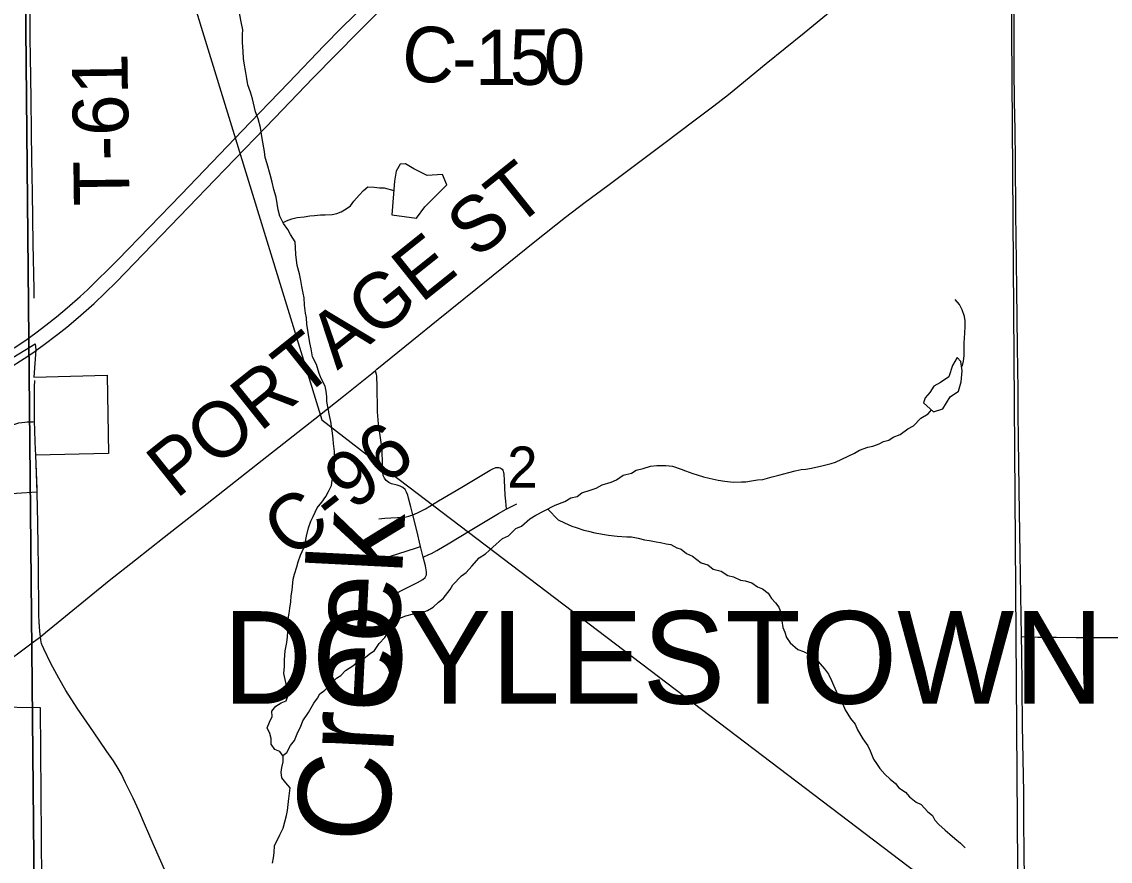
# Model space of a CAD drawing. Extents: x 0 to 34, y -5 to 22.
# Drawn here: x 4.121 to 5.234, y 15.66 to 16.518 of the extents above; entities that cross this region are included whole.
import ezdxf

# ---------------------------------------------------------------- set-up
doc = ezdxf.new("R2010")
doc.units = 0
for name, color, linetype in [('GM_X_City_Street', 7, 'Continuous'), ('GM_X_Corporation', 7, 'Continuous'), ('GM_X_Corporation_Text', 7, 'Continuous'), ('GM_X_County_Road', 7, 'Continuous'), ('GM_X_County_Road_Text', 7, 'Continuous'), ('GM_X_Minor_Lake', 7, 'Continuous'), ('GM_X_Minor_River', 7, 'Continuous'), ('GM_X_Minor_River_Text', 7, 'Continuous'), ('GM_X_Rail_Line', 7, 'Continuous'), ('GM_X_Section', 7, 'Continuous'), ('GM_X_Section_Text', 7, 'Continuous'), ('GM_X_State_Route', 7, 'Continuous'), ('GM_X_Township_Road', 7, 'Continuous'), ('GM_X_Township_Road_Text', 7, 'Continuous')]:
    doc.layers.add(name, color=color, linetype=linetype)

msp = doc.modelspace()

# ---------------------------------------------------------------- linework, layer by layer
at = {"layer": 'GM_X_City_Street'}
msp.add_lwpolyline([(3.9694, 16.021), (3.9748, 16.024), (3.98, 16.0275), (3.9848, 16.0315), (3.9892, 16.0358), (4.002, 16.0495), (4.0089, 16.0558), (4.0138, 16.0596), (4.0189, 16.0632), (4.027, 16.0678), (4.0382, 16.0733), (4.0666, 16.0862), (4.1006, 16.1016), (4.1092, 16.1052), (4.1151, 16.1072), (4.1181, 16.1079), (4.1243, 16.1088), (4.1266, 16.109), (4.1323, 16.1092), (4.1342, 16.1093)], dxfattribs=at)
at = {"layer": 'GM_X_Corporation'}
for points in [[(4.0677, 16.1481), (4.1346, 16.189), (4.1354, 16.1826), (4.1334, 16.1549), (4.2082, 16.1569), (4.2096, 16.0766), (4.1352, 16.075), (4.1366, 16.0371), (4.0945, 16.0344)], [(4.0447, 15.8182), (4.1399, 15.8168), (4.1417, 15.5953), (4.1319, 15.0927)]]:
    msp.add_lwpolyline(points, dxfattribs=at)
at = {"layer": 'GM_X_County_Road'}
for points in [[(4.4841, 16.1629), (4.52, 16.1921), (4.5466, 16.2137), (4.5853, 16.2449), (4.6457, 16.2937), (4.6771, 16.3186), (4.697, 16.3338), (4.7202, 16.3508), (4.7788, 16.3947), (4.8083, 16.4171), (4.8287, 16.4323), (4.8437, 16.4441), (4.8822, 16.4757), (4.9208, 16.5071), (4.9497, 16.5307), (4.9762, 16.5523), (4.9797, 16.5552)], [(5.1431, 15.8894), (5.1418, 15.9739), (5.1415, 15.9955), (5.1408, 16.0387), (5.1404, 16.0677), (5.1401, 16.089), (5.1399, 16.1202), (5.1396, 16.1419), (5.139, 16.1855), (5.1384, 16.2446), (5.1381, 16.273), (5.1373, 16.3223), (5.1372, 16.3402), (5.1371, 16.3594), (5.137, 16.3829), (5.1368, 16.4012), (5.1367, 16.4083), (5.1361, 16.4365), (5.1357, 16.4701), (5.1356, 16.5048), (5.1355, 16.5422), (5.1353, 16.5515), (5.1352, 16.5572)], [(4.1401, 15.8892), (4.1453, 15.8936), (4.2104, 15.9466), (4.2372, 15.968), (4.2665, 15.9911), (4.3106, 16.0256), (4.3619, 16.066), (4.4255, 16.116), (4.4499, 16.1352), (4.4789, 16.1587), (4.4826, 16.1617), (4.4841, 16.1629)], [(4.0964, 15.8566), (4.1332, 15.884), (4.1401, 15.8892)], [(5.1481, 15.4093), (5.148, 15.4361), (5.1478, 15.4766), (5.1478, 15.5357), (5.1472, 15.5849), (5.1465, 15.6221), (5.1459, 15.666), (5.1455, 15.703), (5.1454, 15.7299), (5.1443, 15.7983), (5.1439, 15.8386), (5.1434, 15.8728), (5.1431, 15.8894)]]:
    msp.add_lwpolyline(points, dxfattribs=at)
at = {"layer": 'GM_X_Minor_Lake'}
for points in [[(4.4994, 16.321), (4.5245, 16.3174), (4.5331, 16.3292), (4.5441, 16.3399), (4.5557, 16.3514), (4.5511, 16.362), (4.5356, 16.3612), (4.5218, 16.3679), (4.5135, 16.3731), (4.5078, 16.3727), (4.5037, 16.3655), (4.5022, 16.3552)], [(4.5022, 16.3552), (4.4994, 16.321)], [(5.0532, 16.1194), (5.0626, 16.1225), (5.0701, 16.1347), (5.0788, 16.1405), (5.0814, 16.15), (5.0825, 16.1614), (5.0812, 16.1709), (5.0774, 16.175), (5.0726, 16.1666), (5.0688, 16.1552), (5.0602, 16.1495), (5.0534, 16.1456), (5.0496, 16.1391), (5.0447, 16.1338), (5.0429, 16.1284)], [(5.0429, 16.1284), (5.0532, 16.1194)]]:
    msp.add_lwpolyline(points, dxfattribs=at)
at = {"layer": 'GM_X_Minor_River'}
for points in [[(4.3923, 15.8348), (4.391, 15.8424), (4.3889, 15.8515), (4.3896, 15.8587), (4.3898, 15.8656), (4.3904, 15.8747), (4.3921, 15.8835), (4.3928, 15.8892), (4.393, 15.8946), (4.3929, 15.9003), (4.3932, 15.906), (4.3946, 15.9129), (4.3952, 15.9186), (4.3963, 15.9251), (4.3965, 15.9312), (4.3976, 15.9369), (4.3985, 15.948), (4.3999, 15.9533), (4.4024, 15.9606), (4.4038, 15.9659), (4.406, 15.9728), (4.4093, 15.9801), (4.4107, 15.9851), (4.4121, 15.992), (4.4142, 16.0008), (4.4167, 16.0073), (4.4189, 16.0123), (4.423, 16.0211), (4.4278, 16.0269), (4.4319, 16.0327), (4.4348, 16.0377), (4.4377, 16.0439), (4.4384, 16.0492), (4.4405, 16.058), (4.4408, 16.0648), (4.4409, 16.0789), (4.4399, 16.0869), (4.4395, 16.0918), (4.4386, 16.0975), (4.4372, 16.1093), (4.4356, 16.1157), (4.4343, 16.1226), (4.433, 16.1298), (4.4329, 16.1347), (4.4321, 16.1404), (4.4312, 16.1457), (4.4272, 16.1533), (4.4252, 16.1585), (4.4224, 16.1676), (4.4184, 16.1755), (4.4168, 16.1839), (4.4155, 16.1899), (4.4138, 16.2006), (4.4125, 16.2089), (4.412, 16.2154), (4.4111, 16.2203), (4.4102, 16.2283), (4.4097, 16.2359), (4.4088, 16.2408), (4.4075, 16.2476), (4.4063, 16.2537), (4.405, 16.2605), (4.4025, 16.2692), (4.4012, 16.2802), (4.401, 16.2875), (4.4006, 16.2932), (4.3958, 16.3007), (4.3931, 16.306), (4.3888, 16.312), (4.3848, 16.3195), (4.3832, 16.3259), (4.381, 16.3388), (4.3786, 16.3468), (4.3769, 16.3544), (4.3749, 16.3623), (4.372, 16.3729), (4.37, 16.3794), (4.3691, 16.3858), (4.3669, 16.3991), (4.3652, 16.4101), (4.3627, 16.4192), (4.3599, 16.4264), (4.357, 16.4396), (4.355, 16.4464), (4.3521, 16.454), (4.3513, 16.4604), (4.35, 16.4665), (4.3483, 16.476), (4.3478, 16.4809), (4.3473, 16.4881), (4.3467, 16.4973), (4.3466, 16.5053), (4.3469, 16.5102), (4.3456, 16.5167), (4.3435, 16.5273)], [(4.3883, 16.3129), (4.3918, 16.3147), (4.3971, 16.3167), (4.4027, 16.3183), (4.4096, 16.3188), (4.4156, 16.3197), (4.4202, 16.3202), (4.4263, 16.3207), (4.4312, 16.3208), (4.4385, 16.3213), (4.443, 16.3221), (4.4475, 16.3241), (4.4528, 16.3269), (4.4573, 16.33), (4.4607, 16.3347), (4.4659, 16.3409), (4.4703, 16.3459), (4.4748, 16.3494), (4.4813, 16.3491), (4.4867, 16.3485), (4.4916, 16.3486), (4.5015, 16.3458)], [(5.0819, 16.1655), (5.0828, 16.1666), (5.0839, 16.1712), (5.0845, 16.1769), (5.0844, 16.1834), (5.0847, 16.1898), (5.085, 16.1948), (5.0852, 16.2001), (5.0855, 16.2062), (5.0854, 16.2123), (5.0849, 16.2169), (5.0825, 16.2237), (5.0797, 16.2293), (5.0754, 16.2342)], [(5.0326, 16.1051), (5.0401, 16.1129), (5.0476, 16.1172), (5.0512, 16.1212)], [(4.3878, 15.7676), (4.392, 15.7709), (4.3957, 15.7778), (4.3998, 15.7832), (4.4034, 15.7916), (4.406, 15.7966), (4.4085, 15.8032), (4.4141, 15.8116), (4.4196, 15.8212), (4.4233, 15.8263), (4.4259, 15.8309), (4.4308, 15.8344), (4.4427, 15.8468), (4.4472, 15.8496), (4.4521, 15.8546), (4.4596, 15.8593), (4.4641, 15.8632), (4.469, 15.8656), (4.4761, 15.8714), (4.4817, 15.8753), (4.4865, 15.8823), (4.4921, 15.8885), (4.4973, 15.8966), (4.5029, 15.902), (4.5077, 15.9082), (4.5138, 15.9106), (4.5217, 15.9126), (4.5271, 15.9127), (4.5358, 15.916), (4.5418, 15.9195), (4.547, 15.9245), (4.5519, 15.9284), (4.5589, 15.9377), (4.5619, 15.9423), (4.5705, 15.9516), (4.5754, 15.9548), (4.5813, 15.9614), (4.5888, 15.9699), (4.5952, 15.9742), (4.6026, 15.9808), (4.6127, 15.9897), (4.6188, 15.9925), (4.6262, 15.9999), (4.6319, 16.0023), (4.6405, 16.0097), (4.6465, 16.0136), (4.6552, 16.018), (4.6665, 16.0239), (4.6763, 16.0275), (4.6824, 16.0314), (4.6888, 16.0327), (4.6937, 16.0366), (4.7031, 16.0394), (4.7084, 16.0411), (4.7145, 16.0446), (4.7235, 16.0474), (4.7292, 16.0498), (4.736, 16.0545), (4.7443, 16.0566), (4.7492, 16.0597), (4.7564, 16.0614), (4.7639, 16.0638), (4.7704, 16.0643), (4.7795, 16.0645), (4.7864, 16.0639), (4.7952, 16.0606), (4.7998, 16.0588), (4.8071, 16.0563), (4.8117, 16.0548), (4.8182, 16.0527), (4.8239, 16.0513), (4.8331, 16.0495), (4.84, 16.0485), (4.8484, 16.0475), (4.8568, 16.0477), (4.8613, 16.0478), (4.867, 16.0487), (4.8731, 16.0499), (4.8788, 16.05), (4.8882, 16.0529), (4.8951, 16.0545), (4.9053, 16.0574), (4.9117, 16.059), (4.9178, 16.0603), (4.9227, 16.0608), (4.9284, 16.0616), (4.939, 16.0641), (4.9485, 16.0666), (4.953, 16.0678), (4.9595, 16.071), (4.9723, 16.0769), (4.9776, 16.0801), (4.9862, 16.0833), (4.9912, 16.0842), (4.9976, 16.0866), (5.0021, 16.0889), (5.0074, 16.0902), (5.0119, 16.0933), (5.0191, 16.0961), (5.027, 16.102), (5.0326, 16.1051)], [(4.659, 16.0199), (4.6695, 16.0087), (4.676, 16.0058), (4.6833, 16.0025), (4.6879, 16.0011), (4.6956, 15.9982), (4.7005, 15.9971), (4.707, 15.9954), (4.7208, 15.993), (4.7299, 15.992), (4.7395, 15.9914), (4.7444, 15.9915), (4.7513, 15.9901), (4.7578, 15.9883), (4.7628, 15.9877), (4.7696, 15.9863), (4.7742, 15.9856), (4.7799, 15.9842), (4.7845, 15.9835), (4.7907, 15.9802), (4.7953, 15.9788), (4.8007, 15.9743), (4.8068, 15.9718), (4.8157, 15.9647), (4.8226, 15.9629), (4.828, 15.9585), (4.8361, 15.9563), (4.843, 15.9519), (4.8487, 15.9505), (4.856, 15.9472), (4.8606, 15.9465), (4.8675, 15.9444), (4.8733, 15.9403), (4.8783, 15.9381), (4.8841, 15.9337), (4.8876, 15.9284), (4.8915, 15.9239), (4.895, 15.9194), (4.8974, 15.913), (4.898, 15.9054), (4.8992, 15.8986), (4.9012, 15.894), (4.9028, 15.8884), (4.9068, 15.8831), (4.9145, 15.876), (4.9203, 15.8742), (4.9283, 15.8702), (4.933, 15.8665), (4.9419, 15.8564), (4.9458, 15.8508), (4.949, 15.8443), (4.951, 15.8398), (4.955, 15.8304), (4.9581, 15.8259), (4.9629, 15.8145), (4.9684, 15.8055), (4.9731, 15.7999), (4.9755, 15.7939), (4.981, 15.7848), (4.9861, 15.7777), (4.9885, 15.7724), (4.992, 15.7641), (4.9948, 15.7596), (4.9983, 15.7543), (5.0034, 15.7487), (5.0088, 15.7435), (5.0142, 15.739), (5.0177, 15.7345), (5.0247, 15.7301), (5.0286, 15.7256), (5.0355, 15.72), (5.0405, 15.7175), (5.0475, 15.71), (5.0522, 15.7063), (5.0545, 15.7017), (5.0588, 15.6973), (5.065, 15.6913), (5.07, 15.6872), (5.0751, 15.6827), (5.0809, 15.6779), (5.0855, 15.6734)], [(4.3775, 15.6576), (4.3785, 15.6629), (4.3792, 15.6682), (4.3794, 15.6755), (4.382, 15.6809), (4.3849, 15.6866), (4.3882, 15.6935), (4.39, 15.6997), (4.3917, 15.7065), (4.3928, 15.7115), (4.3941, 15.7237), (4.3947, 15.7291), (4.3954, 15.7348), (4.3911, 15.7396), (4.3868, 15.7449), (4.3863, 15.7506), (4.387, 15.7555), (4.3884, 15.7613), (4.3883, 15.767), (4.3848, 15.7719), (4.3798, 15.7737), (4.3759, 15.7793), (4.3761, 15.785), (4.3745, 15.7903), (4.3721, 15.796), (4.3743, 15.8017), (4.3772, 15.8075), (4.3767, 15.8132), (4.3808, 15.8182), (4.3861, 15.8217), (4.3914, 15.8238), (4.3935, 15.8295), (4.3923, 15.8348)]]:
    msp.add_lwpolyline(points, dxfattribs=at)
at = {"layer": 'GM_X_Rail_Line'}
msp.add_lwpolyline([(4.2939, 16.5478), (4.428, 16.1111), (4.4985, 16.0565), (5.0896, 15.6072), (5.1407, 15.5965), (5.3829, 15.5608), (5.4458, 15.537), (5.4636, 15.5061), (5.4813, 15.3635), (5.5596, 14.8004), (5.5691, 14.7552), (5.5999, 14.7267)], dxfattribs=at)
at = {"layer": 'GM_X_Section'}
for points in [[(5.1327, 16.5549), (5.1393, 15.6065), (4.1342, 15.5936), (4.1248, 16.5469), (4.5534, 16.5511), (5.0529, 16.5543)], [(4.1248, 16.5469), (4.1342, 15.5936), (3.6228, 15.592), (3.1044, 15.6177), (3.0783, 16.5351), (3.1825, 16.5361), (3.5929, 16.5408), (3.9967, 16.5453)]]:
    msp.add_lwpolyline(points, close=True, dxfattribs=at)
at = {"layer": 'GM_X_State_Route'}
for points in [[(4.1132, 16.1849), (4.1251, 16.1927), (4.1355, 16.2002), (4.1457, 16.2079), (4.1564, 16.2165), (4.1674, 16.2256), (4.1806, 16.2373), (4.1882, 16.2443), (4.2192, 16.2749), (4.2839, 16.3418), (4.355, 16.4156), (4.3938, 16.4559), (4.4303, 16.494), (4.4479, 16.5122), (4.4871, 16.5506)], [(4.1348, 16.1815), (4.1356, 16.1821), (4.1427, 16.1871), (4.1578, 16.1987), (4.1671, 16.2061), (4.1787, 16.2157), (4.195, 16.2303), (4.2174, 16.2519), (4.2916, 16.3288), (4.3184, 16.3567), (4.329, 16.3677), (4.3798, 16.4201), (4.4187, 16.4606), (4.4652, 16.5081), (4.4861, 16.5289), (4.5088, 16.551)], [(3.683, 16.0242), (3.6927, 16.0268), (3.7126, 16.0321), (3.9256, 16.0904), (3.9572, 16.0997), (3.973, 16.1043), (3.9927, 16.1107), (4.0005, 16.1133), (4.0136, 16.118), (4.0318, 16.1251), (4.0574, 16.1364), (4.0795, 16.1476), (4.0915, 16.1542), (4.1038, 16.1614), (4.1274, 16.1763), (4.1348, 16.1815)]]:
    msp.add_lwpolyline(points, dxfattribs=at)
at = {"layer": 'GM_X_Township_Road'}
for points in [[(4.1337, 16.2355), (4.1337, 16.2448), (4.1327, 16.2911), (4.1319, 16.3437), (4.1313, 16.3777), (4.131, 16.4053), (4.1305, 16.4395), (4.1301, 16.4828), (4.1298, 16.5013), (4.1297, 16.5168), (4.1295, 16.5414), (4.1294, 16.5476)], [(4.5025, 15.9259), (4.5022, 15.9272), (4.5021, 15.9288), (4.5024, 15.9305), (4.503, 15.9321), (4.5038, 15.9332), (4.5055, 15.9346), (4.5087, 15.9363), (4.5255, 15.9447), (4.531, 15.9477), (4.5334, 15.9497), (4.5348, 15.9524), (4.5349, 15.9555), (4.5337, 15.9616), (4.5316, 15.9706), (4.5288, 15.9817), (4.5249, 15.9979), (4.5209, 16.0139), (4.5188, 16.0221), (4.5166, 16.0311), (4.5156, 16.0341), (4.5145, 16.037), (4.5129, 16.0397), (4.5107, 16.0419), (4.508, 16.0434), (4.505, 16.0443), (4.499, 16.0458), (4.4962, 16.0471), (4.4937, 16.049), (4.4919, 16.0515), (4.4907, 16.0543), (4.4902, 16.0574), (4.4898, 16.0667), (4.4895, 16.0792), (4.4888, 16.0854), (4.4857, 16.107), (4.4849, 16.1194), (4.4845, 16.1474), (4.4842, 16.1536), (4.4839, 16.156), (4.4836, 16.1576), (4.483, 16.1599), (4.4826, 16.1617)], [(4.1342, 16.1093), (4.1341, 16.112), (4.1339, 16.1221), (4.1342, 16.1403), (4.1342, 16.145), (4.1345, 16.1515)], [(4.1354, 16.0745), (4.1349, 16.0883), (4.1345, 16.1006), (4.1342, 16.1093)], [(4.1368, 16.0365), (4.1367, 16.0404), (4.1354, 16.0745)], [(4.4862, 16.0098), (4.4924, 16.0104), (4.5109, 16.0114), (4.5139, 16.0118), (4.5169, 16.0125), (4.5199, 16.0135), (4.5209, 16.0139), (4.5256, 16.0159), (4.5338, 16.0202), (4.547, 16.0282), (4.5708, 16.0424), (4.6001, 16.0596), (4.6028, 16.061), (4.6057, 16.0622), (4.6074, 16.0625), (4.6088, 16.0625), (4.6101, 16.0621), (4.6113, 16.0614), (4.6121, 16.0605), (4.6129, 16.0596), (4.6132, 16.0587), (4.6136, 16.0574), (4.6139, 16.0557), (4.6144, 16.0495), (4.615, 16.0341), (4.6155, 16.0279), (4.6162, 16.0196)], [(4.1401, 15.8892), (4.1396, 15.8949), (4.1389, 15.9042), (4.1386, 15.9118), (4.1386, 15.9207), (4.1384, 15.932), (4.1382, 15.9422), (4.1382, 15.9619), (4.1379, 15.9814), (4.1374, 16.0059), (4.1372, 16.0211), (4.1368, 16.0365)], [(4.5316, 15.9706), (4.5373, 15.9732), (4.5401, 15.9745), (4.5455, 15.9774), (4.5586, 15.9853), (4.5795, 15.998), (4.6084, 16.0153), (4.6162, 16.0196), (4.6191, 16.0212), (4.6273, 16.0253)], [(4.4845, 15.9675), (4.4874, 15.9684), (4.5245, 15.9803), (4.5288, 15.9817)], [(4.2684, 15.648), (4.2554, 15.6774), (4.2465, 15.6977), (4.2406, 15.7115), (4.2348, 15.7242), (4.2272, 15.7399), (4.2229, 15.7485), (4.2196, 15.7545), (4.2149, 15.7621), (4.208, 15.7719), (4.1943, 15.792), (4.1777, 15.816), (4.1661, 15.8342), (4.1588, 15.8468), (4.1508, 15.8618), (4.1436, 15.8767), (4.1419, 15.8805), (4.1416, 15.8812), (4.1413, 15.8822), (4.1409, 15.8837), (4.1401, 15.8892)], [(5.1431, 15.8894), (5.1529, 15.8892), (5.16, 15.8889), (5.1791, 15.8887), (5.1989, 15.8885), (5.2648, 15.8884)]]:
    msp.add_lwpolyline(points, dxfattribs=at)

# ---------------------------------------------------------------- texts
at = {"layer": 'GM_X_Corporation_Text'}
msp.add_text('DOYLESTOWN', height=0.0947, rotation=0, dxfattribs=at).set_placement((4.3265, 15.8207))
at = {"layer": 'GM_X_County_Road_Text'}
for s, height, rotation, p in [('C', 0.0568, 352.3589, (4.5067, 16.4606)), ('1', 0.0568, 0.0545, (4.5846, 16.4536)), ('5', 0.0568, 0.4229, (4.62, 16.4537)), ('0', 0.0568, 0.5074, (4.6551, 16.4539)), ('-', 0.0568, 359.5742, (4.5607, 16.4538)), ('PORTAGE ST', 0.05682, 38.6424, (4.2788, 16.0294)), ('C-96', 0.05682, 38.2338, (4.3967, 15.9673))]:
    msp.add_text(s, height=height, rotation=rotation, dxfattribs=at).set_placement(p)
at = {"layer": 'GM_X_Minor_River_Text'}
msp.add_text('Creek', height=0.09474, rotation=87.0959, dxfattribs=at).set_placement((4.4959, 15.6772))
at = {"layer": 'GM_X_Section_Text'}
msp.add_text('2', height=0.0419, rotation=0, dxfattribs=at).set_placement((4.6173, 16.0419))
at = {"layer": 'GM_X_Township_Road_Text'}
msp.add_text('T-61', height=0.05682, rotation=90.7844, dxfattribs=at).set_placement((4.2312, 16.3303))

doc.saveas('drawing.dxf')
